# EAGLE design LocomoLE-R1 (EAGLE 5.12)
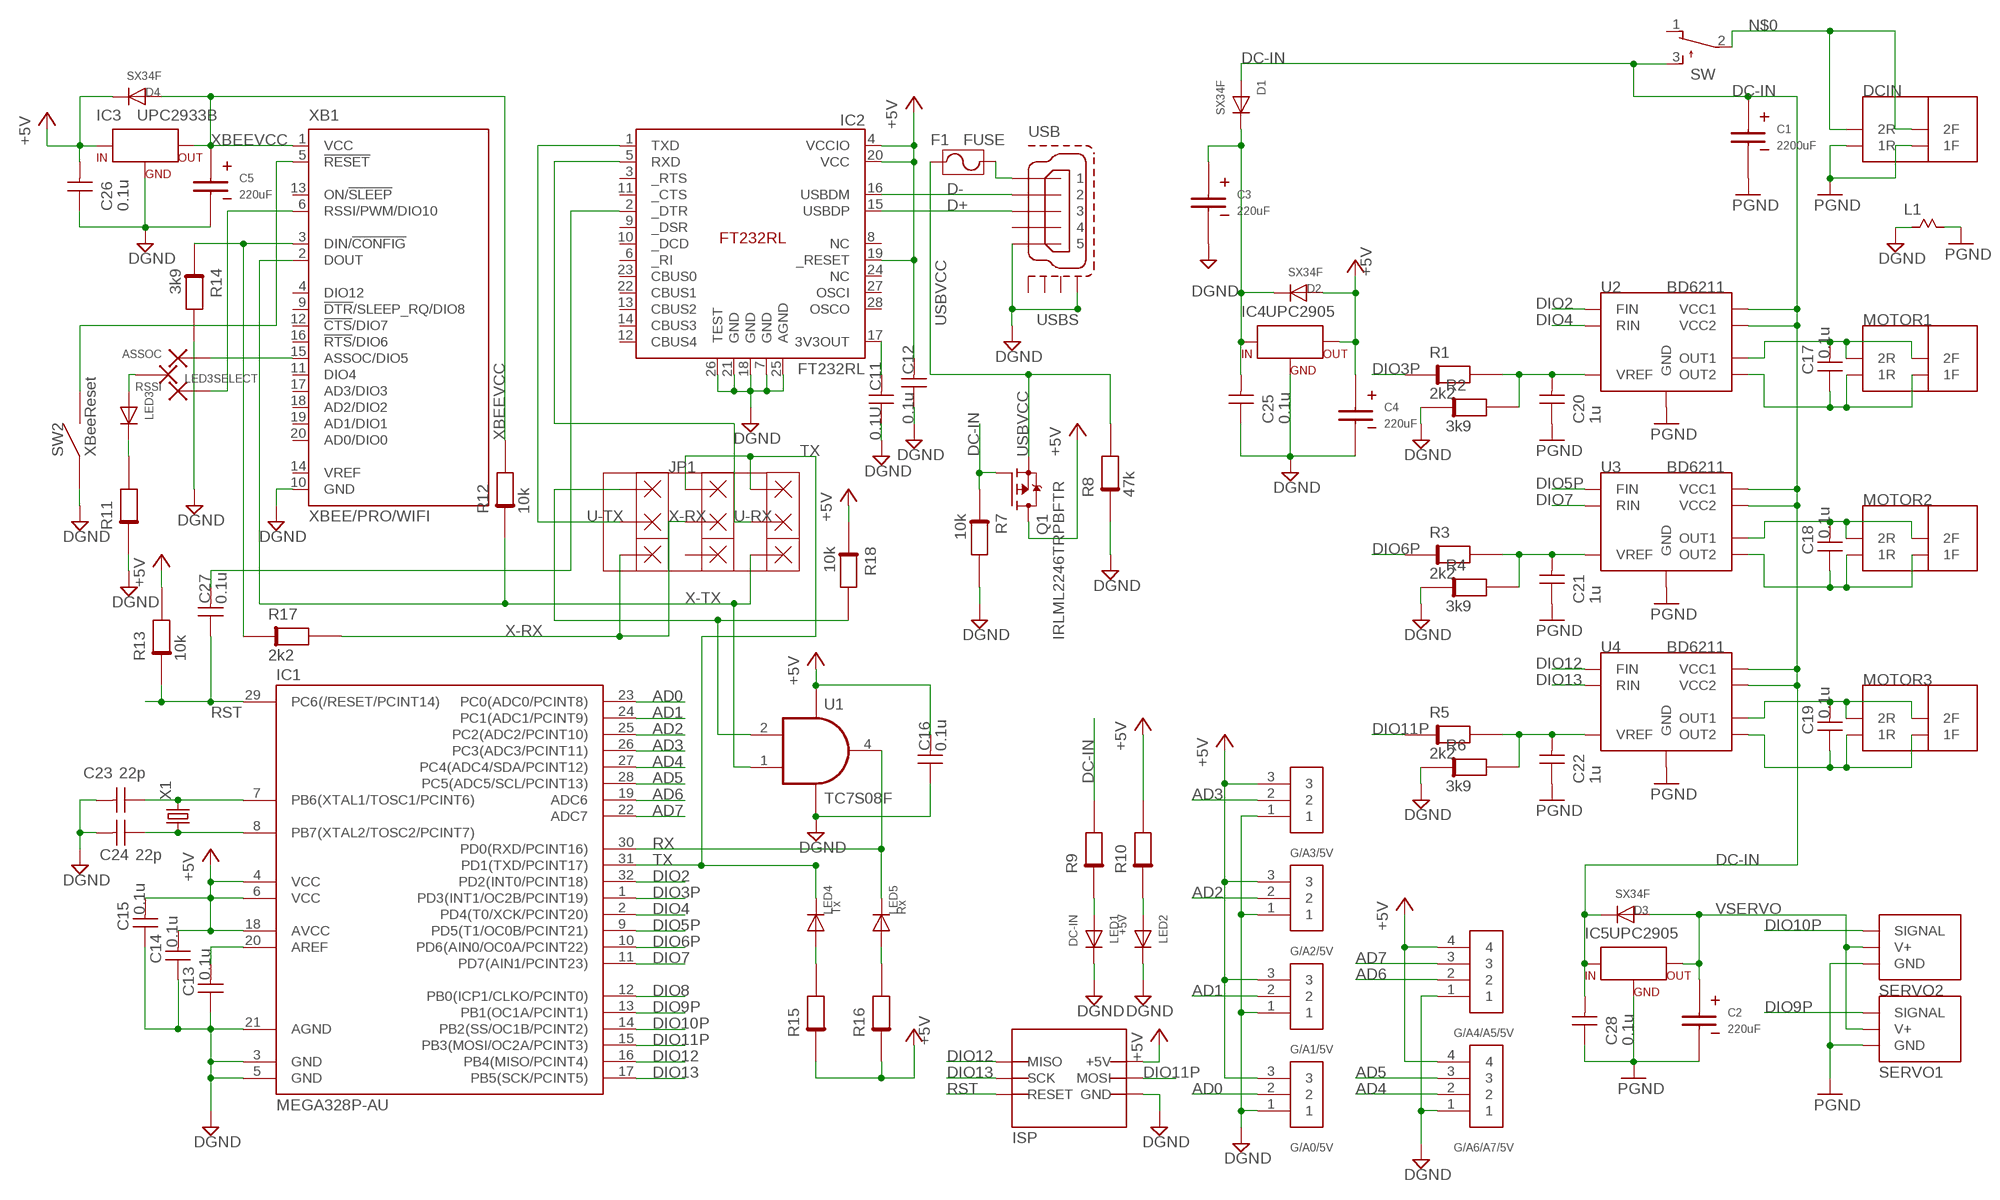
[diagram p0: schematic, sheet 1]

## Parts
ASSOC  PAD  [1,6/0,9]
C1  2200uF  EC5  [C5B2.5]
C2  220uF  EC2.5  [C2.5-3]
C3  220uF  EC2.5  [C2.5-3]
C4  220uF  EC2.5  [C2.5-3]
C5  220uF  EC2.5  [C2.5-3]
C11  0.1U  CAPACITOR1608(B/B)  [1608(B/B)]
C12  0.1u  CAPACITOR1608(B/B)  [1608(B/B)]
C13  0.1u  CAPACITOR1608(B/B)  [1608(B/B)]
C14  0.1u  CAPACITOR1608(B/B)  [1608(B/B)]
C15  0.1u  CAPACITOR1608(B/B)  [1608(B/B)]
C16  0.1u  CAPACITOR1608  [1608]
C17  0.1u  CAPACITOR1608(B/B)  [1608(B/B)]
C18  0.1u  CAPACITOR1608(B/B)  [1608(B/B)]
C19  0.1u  CAPACITOR1608(B/B)  [1608(B/B)]
C20  1u  CAPACITOR1608(B/B)  [1608(B/B)]
C21  1u  CAPACITOR1608(B/B)  [1608(B/B)]
C22  1u  CAPACITOR1608(B/B)  [1608(B/B)]
C23  22p  CAPACITOR1608(B/B)  [1608(B/B)]
C24  22p  CAPACITOR1608(B/B)  [1608(B/B)]
C25  0.1u  CAPACITOR1608(B/B)  [1608(B/B)]
C26  0.1u  CAPACITOR1608(B/B)  [1608(B/B)]
C27  0.1u  CAPACITOR1608  [1608]
C28  0.1u  CAPACITOR1608(B/B)  [1608(B/B)]
D1  SX34F  DIODE-2.5XS34F  [SX34F]
D2  SX34F  DIODE-2.5XS34F  [SX34F]
D3  SX34F  DIODE-2.5XS34F  [SX34F]
D4  SX34F  DIODE-2.5XS34F  [SX34F]
DCIN  TERMINAL-2  [TB401A-1-2-E-TERMINALBLOCK]
F1  FUSE  FUSE5.08  [C-5]
G/A0/5V  S3B-XH-ASTRAIGHT  [B3B-XH-A]
G/A1/5V  S3B-XH-ASTRAIGHT  [B3B-XH-A]
G/A2/5V  S3B-XH-ASTRAIGHT  [B3B-XH-A]
G/A3/5V  S3B-XH-ASTRAIGHT  [B3B-XH-A]
G/A4/A5/5V  S4B-XH-ASTRAIGHT  [B4B-XH-A]
G/A6/A7/5V  S4B-XH-ASTRAIGHT  [B4B-XH-A]
IC1  MEGA328P-AU  MEGA48/88/168-AU  [TQFP32-08]
IC2  FT232RL  [SSOP-28]
IC3  UPC2933B  UPC29XXB_REGULATOR  [SC-64]
IC4  UPC2905  UPC29XXB_REGULATOR  [SC-64]
IC5  UPC2905  UPC29XXB_REGULATOR  [SC-64]
ISP  AVR-ISP  [AVR-ISP]
JP1  JPSW-3P  [JPSW-3P]
L1  INDUCTOR2012  [2012]
LED1  DC-IN  DIODE-2.51608  [1608(DIODE)]
LED2  +5V  DIODE-2.51608  [1608(DIODE)]
LED3  DIODE-2.51608  [1608(DIODE)]
LED3SELECT  PAD  [1,6/0,9]
LED4  Tx  DIODE-2.51608  [1608(DIODE)]
LED5  Rx  DIODE-2.51608  [1608(DIODE)]
MOTOR1  TERMINAL-2  [TB401A-1-2-E-TERMINALBLOCK]
MOTOR2  TERMINAL-2  [TB401A-1-2-E-TERMINALBLOCK]
MOTOR3  TERMINAL-2  [TB401A-1-2-E-TERMINALBLOCK]
Q1  IRLML2246TRPBFTR  IRLML2246TRPBFTR(P-MOSFET)  [SOT23]
R1  2k2  RESISTOR1608  [1608]
R2  3k9  RESISTOR1608  [1608]
R3  2k2  RESISTOR1608  [1608]
R4  3k9  RESISTOR1608  [1608]
R5  2k2  RESISTOR1608  [1608]
R6  3k9  RESISTOR1608  [1608]
R7  10k  RESISTOR1608  [1608]
R8  47k  RESISTOR1608  [1608]
R9  RESISTOR1608  [1608]
R10  RESISTOR1608  [1608]
R11  RESISTOR1608  [1608]
R12  10k  RESISTOR1608  [1608]
R13  10k  RESISTOR1608  [1608]
R14  3k9  RESISTOR1608(B/B)  [1608(B/B)]
R15  RESISTOR1608  [1608]
R16  RESISTOR1608  [1608]
R17  2k2  RESISTOR1608  [1608]
R18  10k  RESISTOR1608(B/B)  [1608(B/B)]
RSSI  PAD  [1,6/0,9]
SERVO1  SERVO-CONNECTER  [SERVO-CONNECTER]
SERVO2  SERVO-CONNECTER  [SERVO-CONNECTER]
SW  TL32PO  [TL3XPO]
SW2  XBeeReset  SW(A_1)SKHLL  [ALPS-SKHLL]
U1  TC7S08F  7SH08F  [SSOP5-0D95]
U2  BD6211  BD621X_MOTOR_DRIVERSO08(B)  [SO08(B/SILK-B)]
U3  BD6211  BD621X_MOTOR_DRIVERSO08(B)  [SO08(B/SILK-B)]
U4  BD6211  BD621X_MOTOR_DRIVERSO08(B)  [SO08(B/SILK-B)]
USB  MINI-USB-SHIELD-  [USB-MINIB-AKIZUKI]
X1  CRYSTALHC49S  [HC49/S]
XB1  XBEE/PRO/WIFI  XBEE-PRO  [XBEE-PRO]

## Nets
+5V: C4.+ C12.P$2 C14.P$2 C15.P$2 C16.2(W) C26.P$2 D2.A D4.K G/A0/5V.3 G/A1/5V.3 G/A2/5V.3 G/A3/5V.3 G/A4/A5/5V.4 G/A6/A7/5V.4 IC1.4(VCC) IC1.6(VCC) IC1.18(AVCC) IC2.4(VCCIO) IC2.19(_RESET) IC2.20(VCC) IC3.1(IN) IC4.3(OUT) ISP.2+5V(+5V) Q1.3(D) R10.2(W) R13.2(W) R15.1 R16.1 R18.P$1 U1.5(VCC)
AD0: G/A0/5V.2 IC1.23(PC0(ADC0/PCINT8))
AD1: G/A1/5V.2 IC1.24(PC1(ADC1/PCINT9))
AD2: G/A2/5V.2 IC1.25(PC2(ADC2/PCINT10))
AD3: G/A3/5V.2 IC1.26(PC3(ADC3/PCINT11))
AD4: G/A6/A7/5V.2 IC1.27(PC4(ADC4/SDA/PCINT12))
AD5: G/A6/A7/5V.3 IC1.28(PC5(ADC5/SCL/PCINT13))
AD6: G/A4/A5/5V.2 IC1.19(ADC6)
AD7: G/A4/A5/5V.3 IC1.22(ADC7)
D+: IC2.15(USBDP) USB.3
D-: IC2.16(USBDM) USB.2
DC-IN: C1.+ C28.P$2 D1.A D3.K IC5.1(IN) Q1.1(G) R7.1 R9.2(W) SW.3(S) U2.2(VCC1) U2.3(VCC2) U3.2(VCC1) U3.3(VCC2) U4.2(VCC1) U4.3(VCC2)
DGND: C3.- C4.- C5.- C11.P$1 C12.P$1 C13.P$1 C14.P$1 C15.P$1 C16.1 C23.P$2 C24.P$2 C25.P$1 C26.P$1 G/A0/5V.1 G/A1/5V.1 G/A2/5V.1 G/A3/5V.1 G/A4/A5/5V.1 G/A6/A7/5V.1 IC1.3(GND) IC1.5(GND) IC1.21(AGND) IC2.7(GND) IC2.18(GND) IC2.21(GND) IC2.25(AGND) IC2.26(TEST) IC3.2(GND) IC4.2(GND) ISP.6GND(GND) L1.1 LED1.K LED2.K R2.1 R4.1 R6.1 R7.2(W) R8.1 R11.1 R14.P$2 SW2.1 U1.3(GND) USB.5 USB.S4 XB1.10(GND)
DIO2: IC1.32(PD2(INT0/PCINT18)) U2.4(FIN)
DIO3P: IC1.1(PD3(INT1/OC2B/PCINT19)) R1.1
DIO4: IC1.2(PD4(T0/XCK/PCINT20)) U2.5(RIN)
DIO5P: IC1.9(PD5(T1/OC0B/PCINT21)) U3.4(FIN)
DIO6P: IC1.10(PD6(AIN0/OC0A/PCINT22)) R3.1
DIO7: IC1.11(PD7(AIN1/PCINT23)) U3.5(RIN)
DIO8: IC1.12(PB0(ICP1/CLKO/PCINT0))
DIO9P: IC1.13(PB1(OC1A/PCINT1)) SERVO1.S(SIGNAL)
DIO10P: IC1.14(PB2(SS/OC1B/PCINT2)) SERVO2.S(SIGNAL)
DIO11P: IC1.15(PB3(MOSI/OC2A/PCINT3)) ISP.4MOSI(MOSI) R5.1
DIO12: IC1.16(PB4(MISO/PCINT4)) ISP.1MISO(MISO) U4.4(FIN)
DIO13: IC1.17(PB5(SCK/PCINT5)) ISP.3SCK(SCK) U4.5(RIN)
GND: C1.- C2.- C20.P$1 C21.P$1 C22.P$1 C28.P$1 DCIN.1F DCIN.1R IC5.2(GND) L1.2(W) SERVO1.GND SERVO2.GND U2.8(GND) U3.8(GND) U4.8(GND) ; supply symbol labelled PGND
N$0: DCIN.2F DCIN.2R SW.2(P)
N$5: LED2.A R10.1
N$6: RSSI.1 XB1.6(RSSI/PWM/DIO10)
N$7: C20.P$2 R1.2(W) R2.2(W) U2.6(VREF)
N$8: C17.P$1 MOTOR1.1F MOTOR1.1R U2.7(OUT2)
N$9: C17.P$2 MOTOR1.2F MOTOR1.2R U2.1(OUT1)
N$10: C3.+ C25.P$2 D1.K D2.K IC4.1(IN)
N$11: C11.P$2 IC2.17(3V3OUT)
N$12: LED1.A R9.1
N$13: C23.P$1 IC1.7(PB6(XTAL1/TOSC1/PCINT6)) X1.2
N$14: C27.2(W) IC2.2(_DTR)
N$15: C18.P$1 MOTOR2.1F MOTOR2.1R U3.7(OUT2)
N$16: C18.P$2 MOTOR2.2F MOTOR2.2R U3.1(OUT1)
N$17: C19.P$2 MOTOR3.2F MOTOR3.2R U4.1(OUT1)
N$18: C19.P$1 MOTOR3.1F MOTOR3.1R U4.7(OUT2)
N$19: C13.P$2 IC1.20(AREF)
N$20: C22.P$2 R5.2(W) R6.2(W) U4.6(VREF)
N$21: ASSOC.1 XB1.15(ASSOC/DIO5)
N$22: C21.P$2 R3.2(W) R4.2(W) U3.6(VREF)
N$23: C24.P$1 IC1.8(PB7(XTAL2/TOSC2/PCINT7)) X1.1
N$24: SW2.2 XB1.5(!RESET)
N$25: JP1.1NC R18.P$2 U1.2(A)
N$26: LED3.A LED3SELECT.1
N$27: F1.P$2 USB.1
N$30: LED3.K R11.2(W)
N$31: R14.P$1 R17.1 XB1.3(DIN/!CONFIG)
N$32: LED4.A R15.2(W)
N$33: LED5.A R16.2(W)
RST: C27.1 IC1.29(PC6(/RESET/PCINT14)) ISP.5RST(RESET) R13.1
RX: IC1.30(PD0(RXD/PCINT16)) LED5.K U1.4(OUT)
TX: IC1.31(PD1(TXD/PCINT17)) JP1.2NC JP1.3NC LED4.K
U-RX: IC2.5(RXD) JP1.3COM
U-TX: IC2.1(TXD) JP1.1COM
USBVCC: F1.P$1 Q1.2(S) R8.2(W)
VSERVO: C2.+ D3.A IC5.3(OUT) SERVO1.V+ SERVO2.V+
X-RX: JP1.1NO JP1.2COM R17.2(W)
X-TX: JP1.3NO R12.1 U1.1(B) XB1.2(DOUT)
XBEEVCC: C5.+ D4.A IC3.3(OUT) R12.2(W) XB1.1(VCC)
Unconnected: IC2.3(_RTS) IC2.6(_RI) IC2.8(NC) IC2.9(_DSR) IC2.10(_DCD) IC2.11(_CTS) IC2.12(CBUS4) IC2.13(CBUS2) IC2.14(CBUS3) IC2.22(CBUS1) IC2.23(CBUS0) IC2.24(NC) IC2.27(OSCI) IC2.28(OSCO) JP1.2NO SW.1(O) USB.4 USB.S1 USB.S2 USB.S3 XB1.4(DIO12) XB1.9(!DTR!/SLEEP_RQ/DIO8) XB1.11(DIO4) XB1.12(!CTS!/DIO7) XB1.13(ON/!SLEEP) XB1.14(VREF) XB1.16(!RTS!/DIO6) XB1.17(AD3/DIO3) XB1.18(AD2/DIO2) XB1.19(AD1/DIO1) XB1.20(AD0/DIO0)

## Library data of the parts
ASSOC LED3SELECT RSSI = beta:PAD
C1-C5 = beta:EC
C11-C28 = beta:CAPACITOR
D1-D4 LED1-LED5 = beta:DIODE-2.5
DCIN MOTOR1-MOTOR3 = beta:TERMINAL-2
F1 = beta:FUSE
G/A0/5V G/A1/5V G/A2/5V G/A3/5V = beta:S3B-XH-A
G/A4/A5/5V G/A6/A7/5V = beta:S4B-XH-A
IC1 = avr-7:MEGA48/88/168
IC2 = ftdi4:FT232RL
IC3-IC5 = beta:UPC29XXB_REGULATOR
ISP = beta:AVR-ISP
JP1 = beta:JPSW-3P
L1 = beta:INDUCTOR
Q1 = beta:IRLML2246TRPBFTR(P-MOSFET)
R1-R18 = beta:RESISTOR
SERVO1 SERVO2 = beta:SERVO-CONNECTER
SW = beta:TL32PO: TINY SWITCH ON - MOM Source: http://www2.produktinfo.conrad.com/datenblaetter/700000-724999/705152-da-01-de-Subminiaturschalter_TL_36YO.pdf
SW2 = beta:SW(A_1)
U1 = 7sh:7SH08: Single AND
U2-U4 = beta:BD621X_MOTOR_DRIVER
USB = beta:MINI-USB-SHIELD-: MINI USB Connector Source: http://www.hirose.co.jp/cataloge_hp/e24000019.pdf
X1 = crystal:CRYSTAL: CRYSTAL
XB1 = beta:XBEE: XBee (TM) /XBee-PRO(TM) OEM RF Modules Source: MaxStream, Inc. xbee_productmanual.pdf; MPN: XBP24-AWI-001; OC_FARNELL: 1337916; OC_NEWARK: 42M2667

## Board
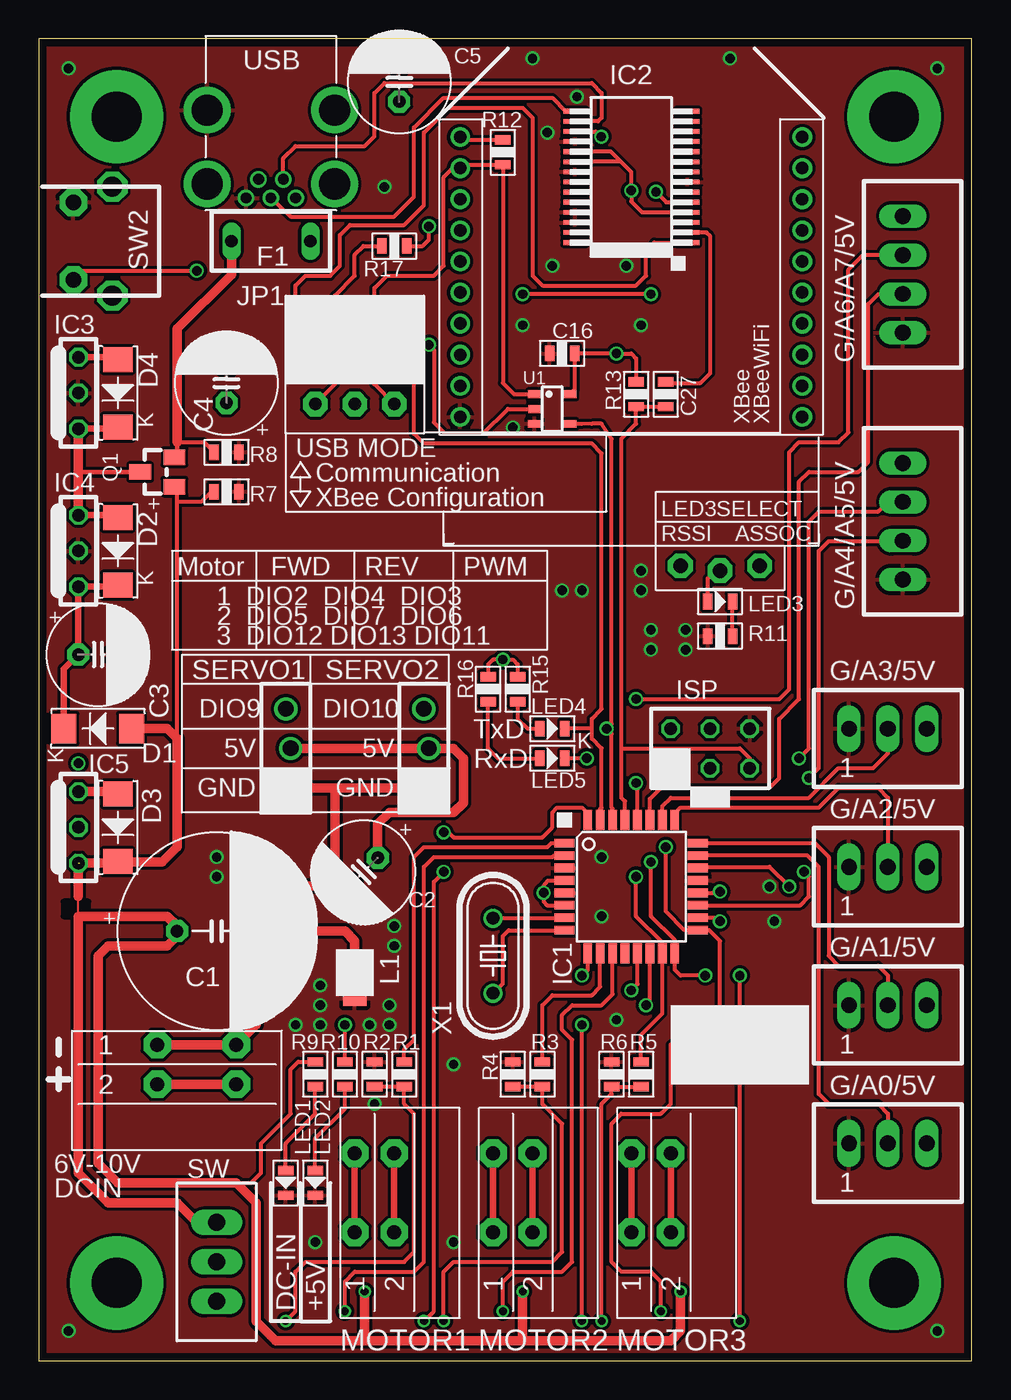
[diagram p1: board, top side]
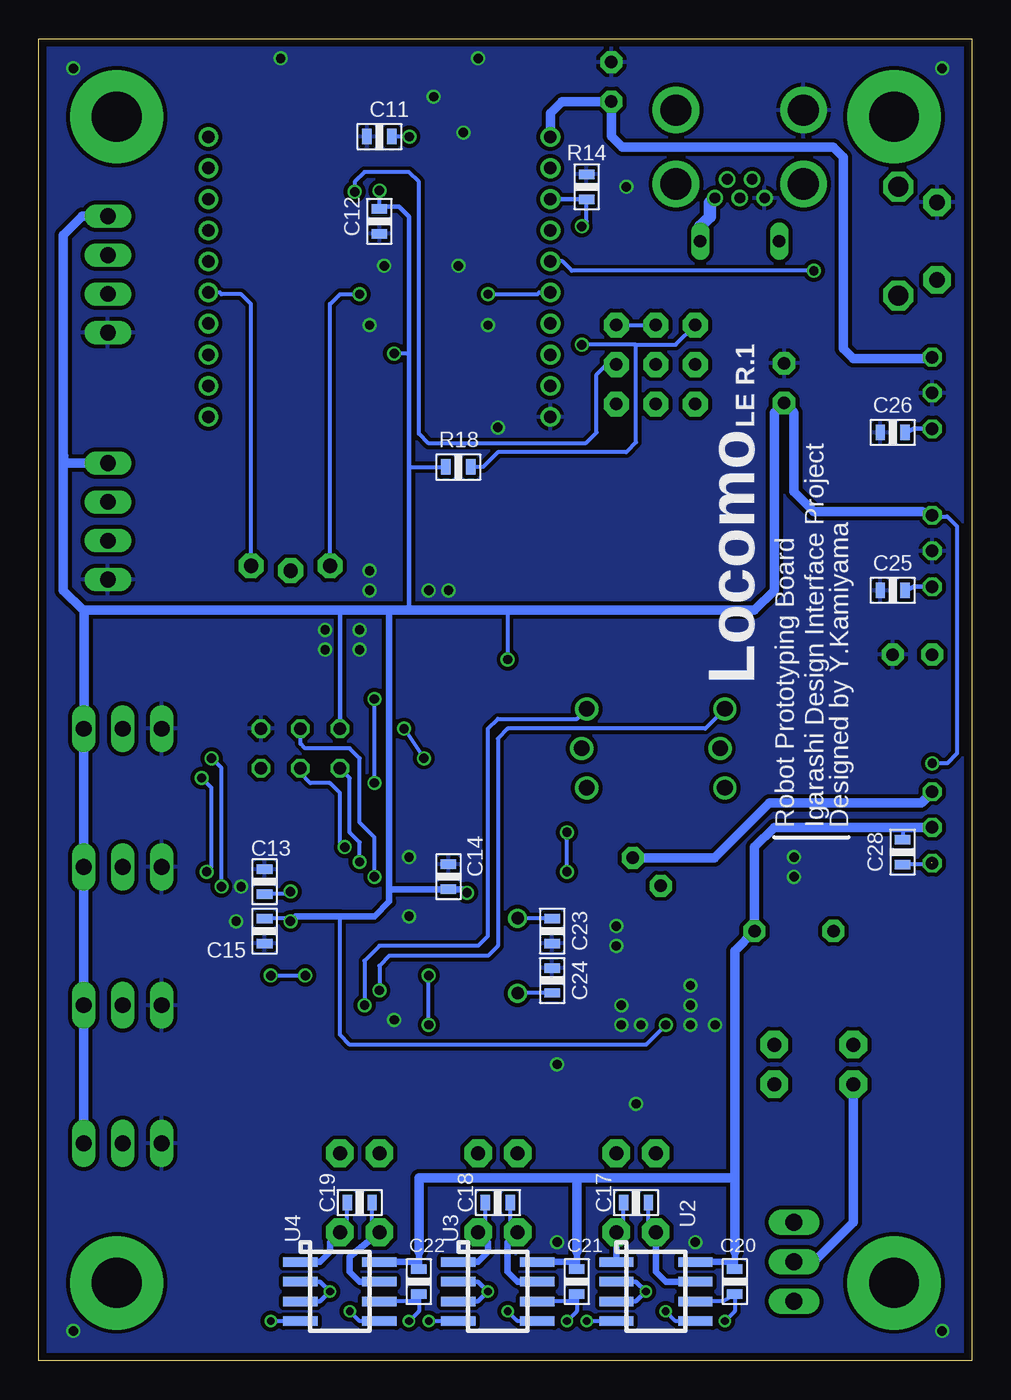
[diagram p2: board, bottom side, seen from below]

Size 60 x 85 mm. Coordinates in mm from the lower left corner, seen from the top.
Outline: 0,0 60,0 60,85 0,85 0,0
Copper layers (1*16): Top 0.035mm / dielectric 1.53mm / Bottom 0.035mm
Design rules "pban_5mil-l2": minimum track width 5mil, minimum drill 0.3mm, track to track 5mil, track to pad 0.229mm, pad to pad 5mil, via to via 5mil, smd to smd 5mil, copper to edge 0.5mm, drill to drill 0.5mm, minimum pad ring 0.15mm, minimum via ring 0.15mm, stop-mask expansion 4mil, vias tented up to drill 0.35mm, thermal gap 10mil
tRestrict: area 1.6,28.6 to 3.2,29.5

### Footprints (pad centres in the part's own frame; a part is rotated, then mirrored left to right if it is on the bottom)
1,6/0,9 = drill 0.914 pad 1.6 octagon: 1 0,0
C5B2.5 = drill 0.8 pad 1.422 octagon: + -2.54,0; - 2.54,0
C2.5-3 = drill 0.8 pad 1.422 octagon: + -1.27,0; - 1.27,0
1608(B/B) = smd 0.6 x 1 bottom: P$1 -0.8,0; P$2 0.8,0
1608 = smd 0.6 x 1: 1 -0.8,0; 2(W) 0.8,0
SX34F = smd 1.6 x 1.9: A -2.15,0; K 2.2,0
TB401A-1-2-E-TERMINALBLOCK = drill 0.9 pad 1.778 octagon: 1F 0,0; 1R 0,5.08; 2F 2.54,0; 2R 2.54,5.08
C-5 = drill 0.8 long: P$1 -2.54,0; P$2 2.54,0
B3B-XH-A = drill 1.016 long: 1 -2.5,0; 2 0,0; 3 2.5,0
B4B-XH-A = drill 1.016 long: 1 -3.75,0; 2 -1.25,0; 3 1.25,0; 4 3.75,0
TQFP32-08 = smd 1.27 x 0.559: 1 -4.293,2.8; 2 -4.293,2; 3 -4.293,1.2; 4 -4.293,0.4; 5 -4.293,-0.4; 6 -4.293,-1.2; 7 -4.293,-2; 8 -4.293,-2.8; 17 4.293,-2.8; 18 4.293,-2; 19 4.293,-1.2; 20 4.293,-0.4; 21 4.293,0.4; 22 4.293,1.2; 23 4.293,2; 24 4.293,2.8 | smd 0.559 x 1.27: 9 -2.8,-4.293; 10 -2,-4.293; 11 -1.2,-4.293; 12 -0.4,-4.293; 13 0.4,-4.293; 14 1.2,-4.293; 15 2,-4.293; 16 2.8,-4.293; 25 2.8,4.293; 26 2,4.293; 27 1.2,4.293; 28 0.4,4.293; 29 -0.4,4.293; 30 -1.2,4.293; 31 -2,4.293; 32 -2.8,4.293
SSOP-28 = smd 0.3 x 1.5: 1 -4.225,-3.625; 2 -3.575,-3.625; 3 -2.925,-3.625; 4 -2.275,-3.625; 5 -1.625,-3.625; 6 -0.975,-3.625; 7 -0.325,-3.625; 8 0.325,-3.625; 9 0.975,-3.625; 10 1.625,-3.625; 11 2.275,-3.625; 12 2.925,-3.625; 13 3.575,-3.625; 14 4.225,-3.625; 15 4.225,3.625; 16 3.575,3.625; 17 2.925,3.625; 18 2.275,3.625; 19 1.625,3.625; 20 0.975,3.625; 21 0.325,3.625; 22 -0.325,3.625; 23 -0.975,3.625; 24 -1.625,3.625; 25 -2.275,3.625; 26 -2.925,3.625; 27 -3.575,3.625; 28 -4.225,3.625
SC-64 = drill 0.8 octagon: 1 -2.3,0; 2 0,0; 3 2.3,0
AVR-ISP = drill 0.8 octagon: 1MISO 0,0; 2+5V 2.54,0; 3SCK 0,-2.54; 4MOSI 2.54,-2.54; 5RST 0,-5.08; 6GND 2.54,-5.08
JPSW-3P = drill 0.8 pad 1.6 octagon: 1COM -2.54,0; 1NC -2.54,2.54; 1NO -2.54,-2.54; 2COM 0,0; 2NC 0,2.54; 2NO 0,-2.54; 3COM 2.54,0; 3NC 2.54,2.54; 3NO 2.54,-2.54
2012 = smd 1 x 1.5: 1 -1.15,0; 2(W) 1.15,0
1608(DIODE) = smd 0.6 x 1: A -0.8,0; K 0.8,0
SOT23 = smd 1 x 1.4: 1 -0.95,-1.1; 2 0.95,-1.1; 3 0,1.1
SERVO-CONNECTER = drill 1 round: GND 0,0; S 0,5.08; V+ 0.318,2.54
TL3XPO = drill 1.1 pad 1.422 long: 1 -2.54,0; 2 0,0; 3 2.54,0
ALPS-SKHLL = drill 1 pad 1.778 octagon: 1 -2.5,0; 2 2.5,0 | drill 1.3 pad 1.93 octagon: S1 -3.5,2.5; S2 3.5,2.5
SSOP5-0D95 = smd 0.8 x 0.5: 1 -1.15,0.95; 2 -1.143,0; 3 -1.15,-0.95; 4 1.15,-0.95; 5 1.15,0.95
SO08(B/SILK-B) = smd 0.6 x 2.2 bottom: 1 -1.905,2.54; 2 -0.635,2.54; 3 0.635,2.54; 4 1.905,2.54; 5 1.905,-2.54; 6 0.635,-2.54; 7 -0.635,-2.54; 8 -1.905,-2.54
USB-MINIB-AKIZUKI = drill 0.7 pad 1 round: 1 -1.6,0; 2 -0.8,-1.2; 3 0,0; 4 0.8,-1.2; 5 1.6,0 | drill 2 round: S1 -4.1,-0.9; S2 4.1,-0.9; S3 -4.1,-5.65; S4 4.1,-5.65
HC49/S = drill 0.813 round: 1 -2.413,0; 2 2.413,0
XBEE-PRO = drill 0.8 pad 1.27 round: 1 -11,9; 2 -11,7; 3 -11,5; 4 -11,3; 5 -11,1; 6 -11,-1; 7 -11,-3; 8 -11,-5; 9 -11,-7; 10 -11,-9; 11 11,-9; 12 11,-7; 13 11,-5; 14 11,-3; 15 11,-1; 16 11,1; 17 11,3; 18 11,5; 19 11,7; 20 11,9

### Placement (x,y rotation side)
ASSOC  46.35,51.12 90 top
C1  11.43,27.62 0 top
C2  20.9,31.43 225 top
C3  3.81,45.4 0 top
C4  12.06,62.87 90 top
C5  23.18,82.23 90 top
C11  38.1,78.71 180 top
C12  38.1,73.26 90 top
C13  45.48,30.8 270 top
C14  33.66,31.11 270 top
C15  45.48,27.62 90 top
C16  33.66,64.77 0 top
C17  21.59,10.16 0 top
C18  30.48,10.16 0 top
C19  39.37,10.16 0 top
C20  15.24,5.08 270 top
C21  25.4,5.08 270 top
C22  35.56,5.08 270 top
C23  26.99,27.62 270 top
C24  26.99,24.45 90 top
C25  5.08,49.53 180 top
C26  5.08,59.69 180 top
C27  40.32,62.15 90 top
C28  4.45,32.7 270 top
D1  3.81,40.64 180 top
D2  5.08,52.07 270 top
D3  5.08,34.29 270 top
D4  5.08,62.23 270 top
DCIN  7.62,20.32 270 top
F1  14.92,71.99 0 top
G/A0/5V  54.61,13.97 0 top
G/A1/5V  54.61,22.86 0 top
G/A2/5V  54.61,31.75 0 top
G/A3/5V  54.61,40.64 0 top
G/A4/A5/5V  55.56,53.98 90 top
G/A6/A7/5V  55.56,69.85 90 top
IC1  38.1,30.48 0 top
IC2  38.1,76.12 90 top
IC3  2.54,62.23 90 top
IC4  2.54,52.07 90 top
IC5  2.54,34.29 90 top
ISP  40.64,38.1 90 top
JP1  20.32,64.06 0 top
L1  20.32,24.45 90 top
LED1  15.88,11.43 270 top
LED2  17.78,11.43 270 top
LED3  43.81,48.81 0 top
LED3SELECT  43.81,50.8 90 top
LED4  33.02,40.64 0 top
LED5  33.02,38.73 0 top
MOTOR1  20.32,8.26 0 top
MOTOR2  29.21,8.26 0 top
MOTOR3  38.1,8.26 0 top
Q1  7.62,57.15 90 top
R1  23.5,18.41 270 top
R2  21.59,18.41 270 top
R3  32.38,18.41 270 top
R4  30.48,18.41 270 top
R5  38.73,18.41 270 top
R6  36.83,18.41 270 top
R7  12.06,55.88 0 top
R8  12.06,58.42 180 top
R9  17.78,18.41 90 top
R10  19.68,18.41 90 top
R11  43.81,46.59 0 top
R12  29.84,77.71 90 top
R13  38.42,62.15 90 top
R14  24.77,75.48 90 top
R15  30.8,43.18 270 top
R16  28.89,43.18 270 top
R17  22.86,71.67 180 top
R18  33.02,57.47 180 top
RSSI  41.27,51.12 90 top
SERVO1  15.88,36.83 0 top
SERVO2  24.77,36.83 0 top
SW  11.43,6.35 90 top
SW2  2.22,71.99 270 top
U1  33.02,61.2 0 top
U2  20.32,4.45 270 top
U3  30.48,4.45 270 top
U4  40.64,4.45 270 top
USB  14.92,74.77 180 top
X1  29.21,26.04 90 top
XB1  38.1,69.69 0 top

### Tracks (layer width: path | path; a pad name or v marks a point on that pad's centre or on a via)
+5V  (via drill 0.6)
  Top 0.254: IC1.18 43.59,28.48 v43.81,28.26 | IC1.4 32.73,30.88 32.46,30.53 v32.46,30.09 32.46,29.53 32.68,29.28 IC1.6 | IC2.4 38.79,73.84 38.1,74.53 v38.1,75.24 38.1,76.44 37.44,77.09 | 37.44,77.09 IC2.20 | IC2.19 36.79,77.75 37.44,77.09 | R16.1 28.89,44.77 29.21,45.09 v29.84,45.09 30.48,45.09 30.8,44.77 R15.1 | R13.2(W) 38.42,64.45 38.1,64.77 v37.15,64.77 C16.2(W) 34.45,62.43 U1.5 | R10.2(W) v19.68,21.59
  Top 0.305: 2.54,57.15 Q1.3
  Top 0.406: IC3.1 4.98,59.93 D4.K | IC4.3 4.93,54.37 D2.A
  Top 0.61: IC4.3 2.54,57.15 IC3.1
  Bottom 0.254: C12.P$2 v38.1,75.24 | 36.2,57.47 R18.P$1 | C15.P$2 43.98,28.42 v43.81,28.26 | 29.84,48.26 v29.84,45.09 | 36.2,64.77 v37.15,64.77 | v19.68,21.59 20.95,20.32 40.01,20.32 40.64,20.95 40.64,28.57 | IC4.3 2.46,54.29 1.59,54.29 0.95,53.66 0.95,39.05 1.59,38.42 v2.54,38.42
  Bottom 0.305: IC3.1 3.69,59.93 C26.P$2 | 36.2,48.26 36.2,57.47 36.2,64.77 36.2,73.58 36.83,74.22 37.95,74.22 C12.P$2 | 40.64,48.26 ISP.2+5V
  Bottom 0.406: v43.81,28.26 43.5,28.57 40.64,28.57 38.42,28.57 37.47,29.53 37.47,30.32 | v32.46,30.09 32.69,30.32 C14.P$2 37.47,30.32 | 37.47,30.32 37.47,48.26
  Bottom 0.61: 57.09,48.26 40.64,48.26 37.47,48.26 36.2,48.26 29.84,48.26 13.97,48.26 12.7,49.53 12.7,60.96 C4.+ 11.43,60.96 11.43,55.88 10.16,54.61 3.17,54.61 IC4.3 2.54,54.61 | 57.09,48.26 57.09,43.2 G/A3/5V.3 G/A2/5V.3 G/A1/5V.3 G/A0/5V.3 | 57.09,48.26 57.15,48.26 58.42,49.53 58.42,58.42 | 58.42,58.42 58.42,72.39 57.21,73.6 G/A6/A7/5V.4 | G/A4/A5/5V.4 58.36,57.73 58.42,58.42
AD0
  Top 0.254: IC1.23 49.44,32.48 50.16,31.75 50.16,17.14 50.8,16.51 53.98,16.51 54.61,15.88 G/A0/5V.2
AD1
  Top 0.254: IC1.24 49.91,33.28 50.8,32.38 50.8,26.04 51.44,25.4 53.98,25.4 54.61,24.77 G/A1/5V.2
AD2
  Top 0.254: IC1.25 40.9,35.19 41.27,35.56 50.16,35.56 51.44,36.83 53.98,36.83 54.61,36.2 G/A2/5V.2
AD3
  Top 0.254: IC1.26 40.1,35.66 40.64,36.2 49.53,36.2 51.44,38.1 53.66,38.1 54.61,39.05 G/A3/5V.2
AD4
  Top 0.254: IC1.27 39.3,36.12 40.01,36.83 46.99,36.83 47.62,37.47 47.62,41.27 48.9,42.55 48.9,56.52 49.53,57.15 52.7,57.15 53.34,57.78 53.34,67.94 53.98,68.58 55.86,68.58 G/A6/A7/5V.2
AD5  (via drill 0.6)
  Top 0.254: IC1.28 38.5,36.75 v38.42,37.15 | v38.42,42.55 47.62,42.55 48.26,43.18 48.26,58.42 48.9,59.05 51.44,59.05 52.07,59.69 52.07,70.17 53.02,71.12 55.86,71.12 G/A6/A7/5V.3
  Bottom 0.254: v38.42,37.15 v38.42,42.55
AD6  (via drill 0.6)
  Top 0.254: v49.53,37.47 50.16,38.1 50.16,52.07 50.8,52.7 55.86,52.7 G/A4/A5/5V.2 | v49.21,31.43 49.53,31.11 49.53,29.84 48.97,29.28 IC1.19
  Bottom 0.254: v49.53,37.47 48.9,36.83 48.9,31.75 v49.21,31.43
AD7  (via drill 0.6)
  Top 0.254: v48.9,38.73 49.53,39.37 49.53,53.98 50.16,54.61 53.98,54.61 54.61,55.24 55.86,55.24 G/A4/A5/5V.3 | v48.26,30.48 46.99,31.75 42.46,31.75 IC1.22
  Bottom 0.254: v48.9,38.73 48.26,38.1 v48.26,30.48
D+
  Top 0.254: USB.3 16.19,73.58 22.86,73.58 24.13,74.85 24.13,79.3 26.04,81.2 33.02,81.2 33.88,80.34 IC2.15
D-
  Top 0.254: IC2.16 35.96,79.69 36.2,79.93 36.2,81.52 35.56,82.15 22.23,82.15 21.59,81.52 21.59,78.74 20.95,78.11 16.51,78.11 15.72,77.32 USB.2
DC-IN  (via drill 0.5)  (1 unrouted)
  Top 0.127: 2.54,28.57 2.54,29.84
  Top 0.254: 8.26,56.52 8.4,56.52 Q1.1 8.89,56.03 8.89,55.24 | R7.1 11.11,55.88 10.48,55.24 8.89,55.24 | 8.89,40.01 8.89,55.24 | R9.2(W) 16.68,19.21 16.19,18.73 16.19,15.88 14.29,13.97 14.29,12.06 13.65,11.43 12.7,11.43
  Top 0.61: v41.27,4.45 41.27,1.91 40.64,1.27 31.11,1.27 | 20.95,1.27 31.11,1.27 | 31.11,1.27 v31.11,4.45 | 20.95,1.27 v20.95,4.45 | 20.95,1.27 15.24,1.27 13.97,2.54 13.97,10.16 12.7,11.43 5.08,11.43 3.81,12.7 3.81,26.04 4.45,26.67 8.26,26.67 8.89,27.3 C1.+ 8.89,27.94 8.26,28.57 2.54,28.57 2.54,12.06 4.45,10.16 8.89,10.16 10.16,8.89 SW.3 | 6.35,40.64 D1.A 8.26,40.64 8.89,40.01 8.89,33.02 7.94,32.07 5.1,32.07 D3.K 4.98,31.99 IC5.1 2.54,29.84
  Bottom 0.254: C28.P$2 2.54,31.9 IC5.1
  Bottom 0.305: U4.2 41.91,5.08 v41.27,4.45 41.91,3.81 U4.3 | U3.2 31.75,5.08 v31.11,4.45 31.75,3.81 U3.3 | U2.3 21.59,3.81 v20.95,4.45 21.59,5.08 U2.2
  Bottom 0.61: 2.62,31.99 2.62,32.07
DGND  (via drill 0.6)
  other vias: 36.2,28.57 26.67,19.05 37.15,21.91 17.78,7.62 47.31,28.26 11.43,32.38 26.67,7.62 22.54,21.59 22.54,22.86 18.1,21.59 18.1,24.13 39.37,46.99 39.37,45.72 32.7,78.98 41.59,46.99 41.59,45.72 57.78,83.11 1.91,83.11 57.78,1.91 1.91,1.91 37.78,70.41 33.02,70.41 44.45,83.74 30.48,60.01 21.59,16.51 11.43,31.11 18.1,22.86 33.66,49.53 34.92,49.53 38.73,49.53 38.73,50.8 22.23,75.48 31.75,83.74 38.73,66.59 31.11,66.59 46.99,30.48 36.2,32.38 21.27,21.59 16.51,21.59 22.86,26.67 22.86,27.94 34.61,81.28
  pour Top (isolate 0.2): -2.54,-2.54 62.23,-2.54 62.23,86.36 -2.54,86.36
  pour Bottom (isolate 0.25): -1.27,-2.54 66.04,-2.54 66.04,87.63 -1.27,86.36
DIO2  (via drill 0.5, 0.6)
  Top 0.254: v24.77,2.54 25.4,3.17 25.4,30.8 v26.04,31.43 | IC1.32 35.3,35.19 34.92,35.56 33.34,35.56 33.02,35.24 33.02,34.29 32.38,33.66 26.67,33.66 26.35,33.97 v26.04,33.97
  Bottom 0.254: U2.4 v24.77,2.54 | v26.04,31.43 v26.04,33.97
DIO3P
  Top 0.254: IC1.1 32.96,33.28 32.7,33.02 24.77,33.02 24.13,32.38 24.13,20.64 23.5,20 R1.1
DIO4  (via drill 0.5)
  Top 0.254: v19.68,3.17 19.68,5.08 20.32,5.71 24.13,5.71 24.77,6.35 24.77,31.75 25.4,32.38 33.02,32.38 33.12,32.48 IC1.2
  Bottom 0.254: U2.5 19.05,2.54 v19.68,3.17
DIO5P  (via drill 0.5, 0.6)
  Top 0.254: IC1.9 35.3,25.14 v34.92,24.77 | v34.92,2.54 v34.92,21.59
  Bottom 0.254: U3.4 v34.92,2.54 | v34.92,21.59 v34.92,24.77
DIO6P
  Top 0.254: IC1.10 36.1,24.04 35.56,23.5 33.02,23.5 32.38,22.86 R3.1
DIO7  (via drill 0.5)
  Top 0.254: v29.84,3.17 29.84,5.08 30.48,5.71 33.66,5.71 34.29,6.35 34.29,20.64 33.66,21.27 33.66,22.23 34.29,22.86 36.2,22.86 36.9,23.57 IC1.11
  Bottom 0.254: U3.5 29.21,2.54 v29.84,3.17
DIO9P  (via drill 0.6)
  Top 0.254: IC1.13 38.5,24.21 v38.1,23.81
  Bottom 0.254: v38.1,23.81 38.1,25.4 37.47,26.04 31.11,26.04 30.48,26.67 30.48,40.01 29.84,40.64 17.14,40.64 SERVO1.S
DIO10P  (via drill 0.6)
  Top 0.254: IC1.14 39.3,23.11 v39.05,22.86
  Bottom 0.254: v39.05,22.86 39.05,25.72 38.1,26.67 31.75,26.67 31.11,27.3 31.11,40.64 30.48,41.27 25.4,41.27 SERVO2.S
DIO11P  (via drill 0.6)
  Top 0.254: v38.42,31.11 38.42,28.57 40.1,26.89 IC1.15 40.1,22.32 38.73,20.95 R5.1
  Bottom 0.254: ISP.4MOSI 43.18,39.69 42.86,39.37 40.01,39.37 39.37,38.73 39.37,34.61 38.42,33.66 v38.42,31.11
DIO12  (via drill 0.5, 0.6)
  Top 0.254: v45.09,2.54 v45.09,24.77 | v39.37,32.07 39.37,28.57 40.9,27.05 IC1.16 40.9,25.14 41.27,24.77 v42.86,24.77
  Bottom 0.254: U4.4 v45.09,2.54 | ISP.1MISO 40.01,37.47 40.01,33.97 39.37,33.34 v39.37,32.07 | v45.09,24.77 v42.86,24.77
DIO13  (via drill 0.5, 0.6)
  Top 0.254: v40.01,3.17 40.01,5.08 39.37,5.71 37.47,5.71 36.83,6.35 36.83,15.24 37.47,15.88 40.01,15.88 40.64,16.51 40.64,20.32 41.27,20.95 43.18,20.95 43.81,21.59 43.81,26.99 43.12,27.68 IC1.17 41.53,27.68 40.32,28.89 v40.32,33.02
  Bottom 0.254: U4.5 39.37,2.54 v40.01,3.17 | ISP.3SCK 43.18,37.78 42.55,37.15 41.27,37.15 40.64,36.51 40.64,33.34 v40.32,33.02
GND
  Top 0.61: DCIN.1F DCIN.1R 13.97,21.59 C1.- | L1.2(W) 20.32,26.99 19.68,27.62 C1.- | C1.- 13.97,29.84 14.66,30.53 C2.- 19.05,31.49 19.05,36.83 | 19.05,36.83 SERVO1.GND | 19.05,36.83 SERVO2.GND
  Bottom 0.254: 4.45,34.29 C28.P$1
  Bottom 0.406: U4.8 35.68,6.35 C22.P$1 35.56,6.99 | U3.8 25.52,6.35 C21.P$1 25.4,6.99 | U2.8 15.36,6.35 C20.P$1 15.24,6.99
  Bottom 0.61: 35.56,6.99 35.56,11.75 25.4,11.75 | 25.4,11.75 25.4,6.99 | 15.24,11.75 25.4,11.75 | 15.24,6.99 15.24,11.75 | 15.24,11.75 15.24,26.35 C1.- 13.97,33.02 12.7,34.29 4.45,34.29 IC5.2
N$0
  Top 0.61: DCIN.2F DCIN.2R
  Bottom 0.61: SW.2 10.16,6.35 7.62,8.89 DCIN.2F
N$1  (via drill 3.2 pad 6)
  other vias: 5,80
N$2  (via drill 3.2 pad 6)
  other vias: 55,80
N$3  (via drill 3.2 pad 6)
  other vias: 55,5
N$4  (via drill 3.2 pad 6)
  other vias: 5,5
N$5
  Top 0.254: LED2.A 17.78,14.29 19.68,16.19 R10.1
N$6  (via drill 0.6)
  Top 0.254: v39.37,68.58 v31.11,68.58
  Bottom 0.254: XB1.6 27.83,68.69 27.94,68.58 v31.11,68.58 | v39.37,68.58 40.64,68.58 41.27,67.94 RSSI.1
N$7  (via drill 0.5)
  Top 0.254: v15.88,2.54 16.51,3.17 16.51,5.71 17.14,6.35 23.5,6.35 24.13,6.99 24.13,15.88 23.5,16.51 R1.2(W) R2.2(W)
  Bottom 0.254: U2.6 15.99,3.81 C20.P$2 15.24,3.17 v15.88,2.54
N$8
  Top 0.406: MOTOR1.1F MOTOR1.1R
  Bottom 0.254: C17.P$1 20.79,8.72 MOTOR1.1F
  Bottom 0.406: U2.7 19.68,5.08 20.32,5.71 MOTOR1.1F
N$9
  Top 0.406: MOTOR1.2F MOTOR1.2R
  Bottom 0.254: C17.P$2 22.39,8.72 MOTOR1.2F
  Bottom 0.406: U2.1 MOTOR1.2F
N$10
  Top 0.406: D1.K 1.61,44.47 C3.+ IC4.1 4.98,49.77 D2.K
  Bottom 0.305: IC4.1 3.69,49.77 C25.P$2
N$11  (via drill 0.6)
  Top 0.254: IC2.17 35.81,79.05 v36.17,78.71
  Bottom 0.254: v36.17,78.71 C11.P$2
N$12
  Top 0.254: LED1.A 15.88,13.97 17.78,15.88 R9.1
N$13
  Top 0.254: IC1.7 29.24,28.48 X1.2
  Bottom 0.254: C23.P$1 29.18,28.42 X1.2
N$14
  Top 0.254: IC2.2 42.95,72.55 43.18,72.31 43.18,63.5 42.55,62.87 40.41,62.87 C27.2(W)
N$15
  Top 0.406: MOTOR2.1F MOTOR2.1R
  Bottom 0.254: C18.P$1 29.68,8.72 MOTOR2.1F
  Bottom 0.406: U3.7 29.21,5.08 29.84,5.71 29.84,7.62 MOTOR2.1F
N$16
  Top 0.406: MOTOR2.2F MOTOR2.2R
  Bottom 0.254: C18.P$2 31.28,8.72 MOTOR2.2F
  Bottom 0.406: U3.1 31.75,6.35 31.11,6.99 31.11,7.62 MOTOR2.2F
N$17
  Top 0.406: MOTOR3.2F MOTOR3.2R
  Bottom 0.254: C19.P$2 40.17,8.72 MOTOR3.2F
  Bottom 0.406: U4.1 41.91,6.35 41.27,6.99 41.27,7.62 MOTOR3.2F
N$18
  Top 0.406: MOTOR3.1F MOTOR3.1R
  Bottom 0.254: C19.P$1 38.57,8.72 MOTOR3.1F
  Bottom 0.406: U4.7 39.37,5.08 40.01,5.71 40.01,6.67 MOTOR3.1F
N$19  (via drill 0.6)
  Top 0.254: IC1.20 43.41,30.08 v43.81,30.16
  Bottom 0.254: C13.P$2 43.98,30 v43.81,30.16
N$20  (via drill 0.5)
  Top 0.254: R5.2(W) R6.2(W) 36.83,17.14 36.2,16.51 v36.2,2.54
  Bottom 0.254: U4.6 35.68,3.81 C22.P$2 35.56,3.17 v36.2,2.54
N$21
  Bottom 0.254: XB1.15 48.37,68.69 48.26,68.58 46.99,68.58 46.35,67.94 ASSOC.1
N$22  (via drill 0.5)
  Top 0.254: v26.04,2.54 26.04,5.71 26.67,6.35 33.02,6.35 33.66,6.99 33.66,15.24 32.38,16.51 R3.2(W) R4.2(W)
  Bottom 0.254: U3.6 25.52,3.81 C21.P$2 25.4,3.17 v26.04,2.54
N$23
  Top 0.254: IC1.8 30.22,27.68 29.84,27.3 29.84,24.26 X1.1
  Bottom 0.254: C24.P$1 29.18,23.65 X1.1
N$24  (via drill 0.6)
  Top 0.254: v10.16,70.09 2.86,70.09 2.54,69.77 2.5,69.77 SW2.2
  Bottom 0.254: XB1.5 26.32,70.69 25.72,70.09 v10.16,70.09
N$25  (via drill 0.6)
  Top 0.254: U1.2 30.16,61.2 28.57,59.61 26.11,59.61 25.4,60.33 25.4,65.01 v25.08,65.33
  Bottom 0.254: JP1.1NC 19.05,65.33 21.59,65.33 | 21.59,65.33 v25.08,65.33 | R18.P$2 31.43,57.47 30.48,58.42 22.23,58.42 21.59,59.05 21.59,65.33
N$26
  Top 0.254: LED3.A 43.02,50.32 LED3SELECT.1
N$27
  Bottom 0.813: F1.P$2 17.46,72.94 16.83,73.58 16.83,74.47 USB.1
N$30
  Top 0.254: R11.2(W) LED3.K
N$31  (via drill 0.6)
  Top 0.254: R17.1 24.68,71.67 25.08,72.07 v25.08,72.94
  Bottom 0.254: R14.P$1 24.77,73.26 v25.08,72.94
  Bottom 0.305: XB1.3 R14.P$1
N$32
  Top 0.254: LED4.A 31.43,40.64 30.8,41.27 R15.2(W)
N$33
  Top 0.254: LED5.A 29.53,38.73 28.89,39.37 R16.2(W)
RST
  Top 0.254: IC1.29 37.7,35.96 37.47,36.2 37.47,39.37 | C27.1 R13.1 38.42,60.24 37.47,59.29 37.47,39.37 | 37.47,39.37 45.09,39.37 45.72,38.73 ISP.5RST
RX  (via drill 0.6)
  Top 0.254: IC1.30 36.9,35.49 36.83,35.56 36.83,40.32 v36.51,40.64 36.83,40.96 36.83,59.29 36.2,60.24 35.56,60.24 34.93,60.24 U1.4 | v35.24,38.73 LED5.K
  Bottom 0.254: v36.51,40.64 v35.24,38.73
TX
  Top 0.254: IC1.31 36.1,35.47 36.2,35.56 36.2,39.37 35.56,40.01 35.56,40.64 | 35.56,40.64 35.56,41.27 36.2,41.91 36.2,58.34 35.56,58.98 24.77,58.98 24.13,59.61 24.13,65.96 23.5,66.59 JP1.3NC | 35.56,40.64 LED4.K
  Bottom 0.254: JP1.3NC JP1.2NC
U-RX  (via drill 0.6)
  Top 0.254: IC2.5 40.36,74.5 v39.69,75.17
  Bottom 0.254: v39.69,75.17 39.69,75.8 39.05,76.44 36.2,76.44 35.56,75.8 35.56,59.61 34.92,58.97 34.92,58.98 24.84,58.98 24.13,59.69 24.13,63.42 23.5,64.06 JP1.3COM
U-TX
  Top 0.254: IC2.1 39.59,71.89 39.05,71.36 39.05,69.77 38.42,69.14 32.38,69.14 31.75,69.77 31.75,79.93 31.11,80.56 26.35,80.56 24.77,78.98 24.77,74.3 23.5,73.03 20,73.03 19.37,72.39 19.37,70.41 18.73,69.77 17.14,69.77 16.51,69.14 16.51,65.33 JP1.1COM
USBVCC
  Top 0.254: 8.89,59.05 10.63,59.05 R8.2(W)
  Top 0.305: Q1.2 8.89,58.27 8.89,59.05
  Top 0.61: 8.89,59.05 8.89,66.36 12.38,69.85 F1.P$1
VSERVO
  Top 0.61: IC5.3 4.93,36.59 D3.A 5.15,36.51 | SERVO1.V+ SERVO2.V+ 26.67,39.37 27.3,38.73 27.3,35.88 26.67,35.24 22.54,35.24 21.8,34.5 C2.+
  Bottom 0.61: IC5.3 3.25,35.88 13.02,35.88 16.56,32.33 C2.+
X-RX
  Top 0.254: 19.05,64.06 JP1.2COM | 19.05,64.06 19.05,68.5 20.32,69.77 20.32,71.12 20.88,71.67 R17.2(W) | JP1.1NO 19.05,62.78 19.05,64.06
X-TX
  Top 0.254: JP1.3NO 21.59,62.78 21.59,68.98 22.38,69.77 25.4,69.77 26.04,70.41 26.04,76.12 26.61,76.69 XB1.2 27.32,76.91 R12.1 29.84,62.87 30.56,62.15 U1.1
XBEEVCC
  Top 0.254: R12.2(W) 27.28,78.51 XB1.1
  Top 0.406: IC3.3 4.93,64.53 D4.A
  Bottom 0.61: XB1.1 27.1,80.22 26.35,80.96 C5.+ 23.18,78.74 22.46,78.03 8.89,78.03 8.26,77.39 8.26,65.09 7.62,64.45 2.62,64.45 IC3.3

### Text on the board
tPlace: K | XBee | XBeeWiFi | + | + | K | + | K | K | + | +
tNames: USB MODE | Communication | XBee Configuration | Motor | FWD | REV | PWM | 1 DIO2 DIO4 DIO3 | 2 DIO5 DIO7 DIO6 | 3 DIO12 DIO13 DIO11 | DIO9 | DIO10 | 5V | 5V | TxD | RxD | GND | GND | 6V-10V | DC-IN | +5V
bNames: LE R.1 | Locomo | Designed by Y.Kamiyama | Igarashi Design Interface Project | Robot Prototyping Board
